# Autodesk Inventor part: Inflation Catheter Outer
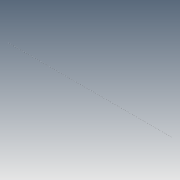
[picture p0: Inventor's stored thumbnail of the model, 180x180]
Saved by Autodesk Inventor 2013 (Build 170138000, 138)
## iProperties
Created: 2013-11
Part Number: Inflation Catheter Outer
Material: Generic
Document SubType Name: Modeling
Designer: Warren
Density: 1 g/cm^3
Author: Warren
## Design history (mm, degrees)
sketch "Sketch1"
  geometry: C1 r 0.15 at (0, 0); C2 r 0.1 at (0, 0); 1 further point
  constraints: 2 centre point, 2 coincident
  dimensions: "d0" = 0.3 diameter of C1; "d2" = 0.2 diameter of C2
extrude "Extrusion1" new body sketch "Sketch1" distance "d3" = 450; taper "d4" = 0 deg
body "Solid1"
